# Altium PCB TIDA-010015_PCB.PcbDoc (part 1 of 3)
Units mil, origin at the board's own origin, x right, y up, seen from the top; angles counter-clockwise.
Board outline 6299.21 x 3149.61 mil, 2 copper layers (Top Layer, Bottom Layer), stack 64.6 mil thick; 232 components, 110 nets, 524 pads, 83 vias.
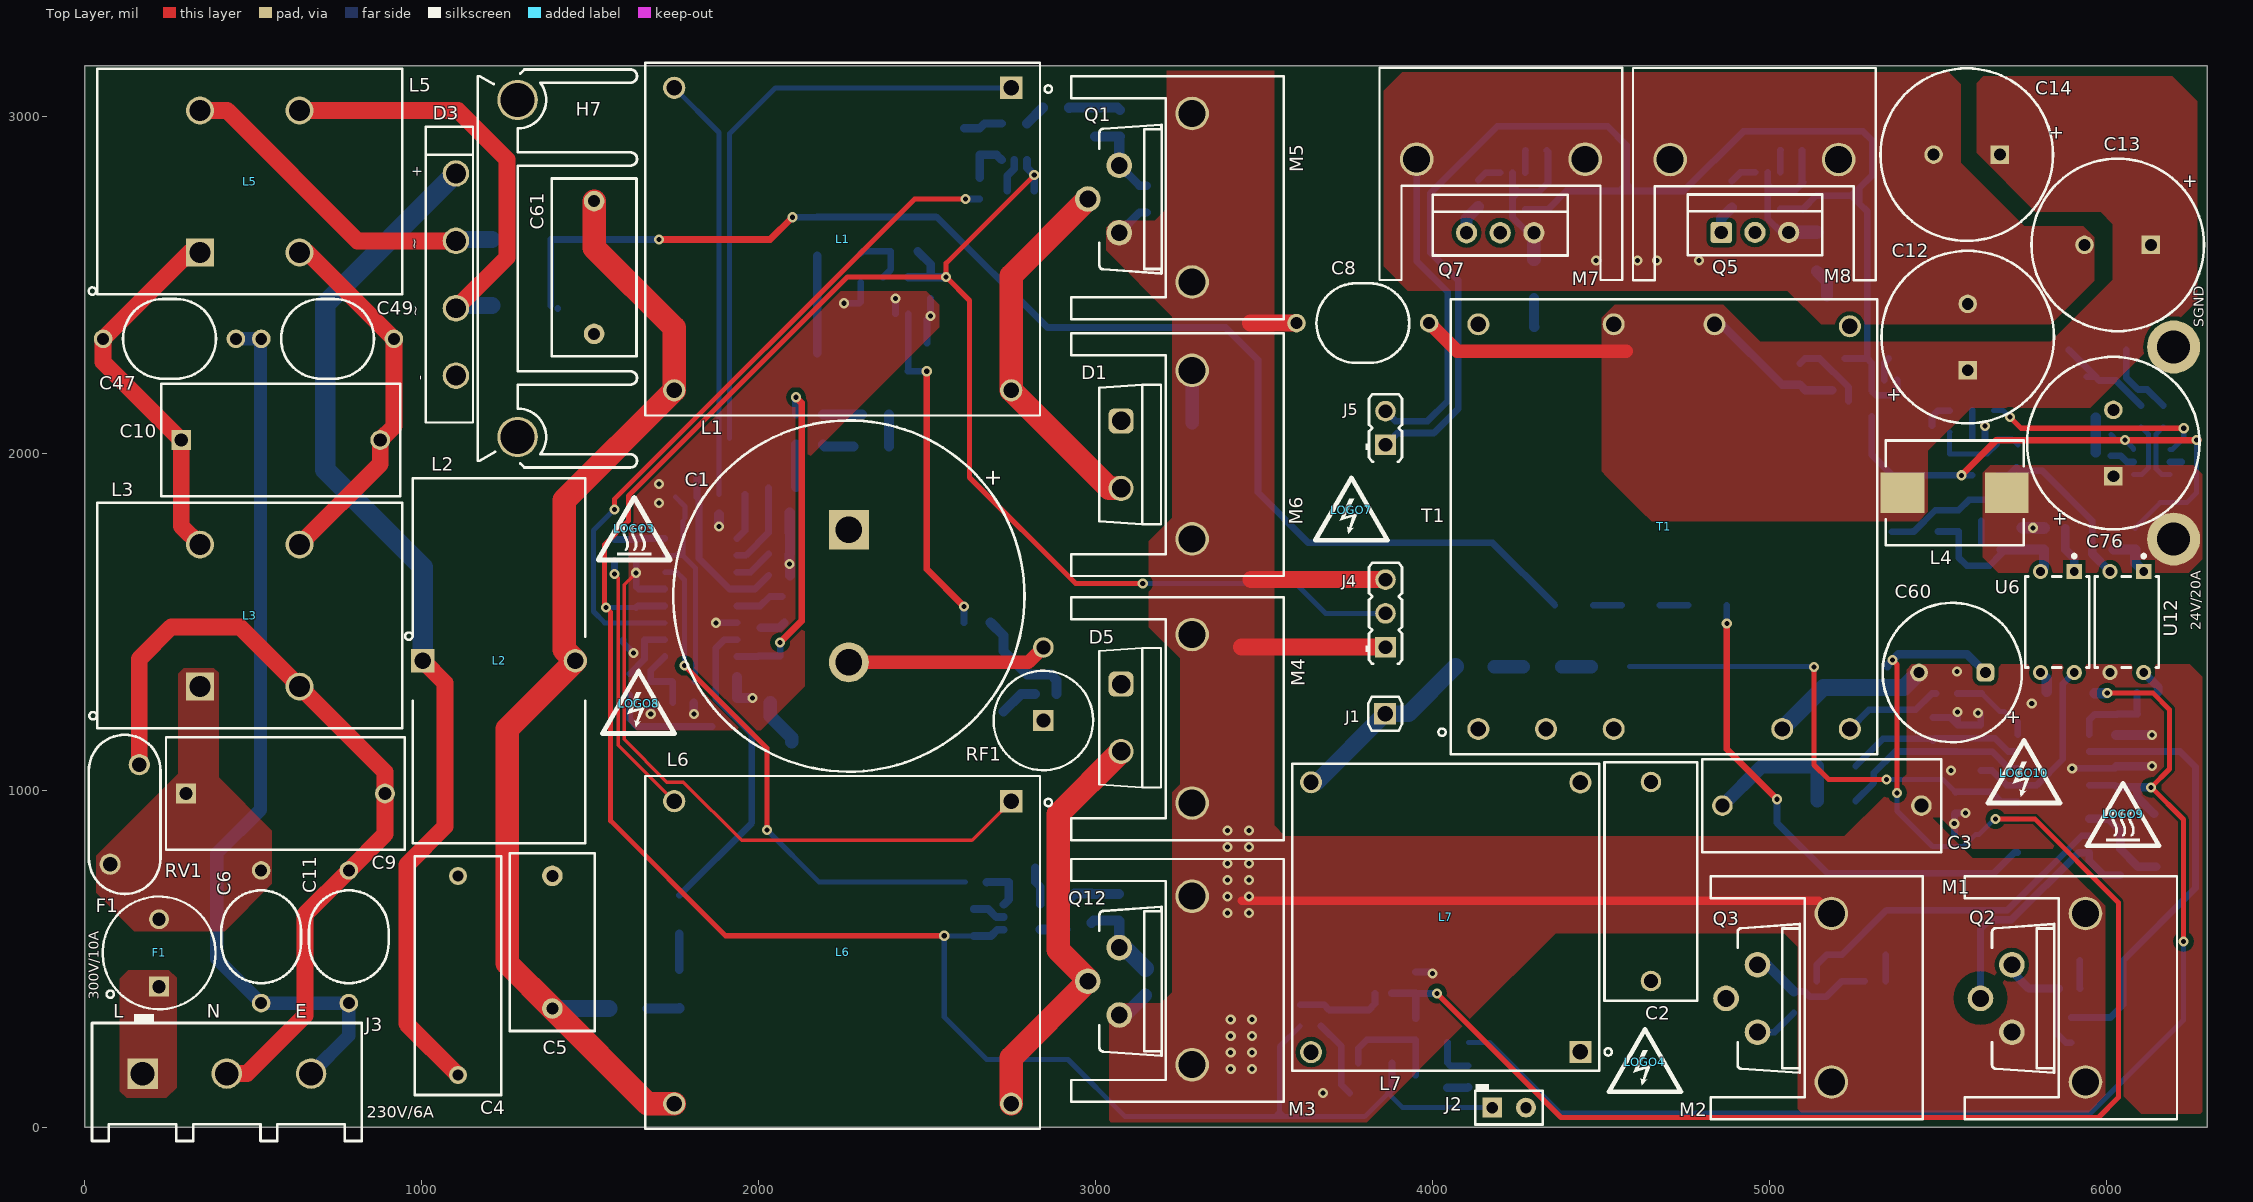
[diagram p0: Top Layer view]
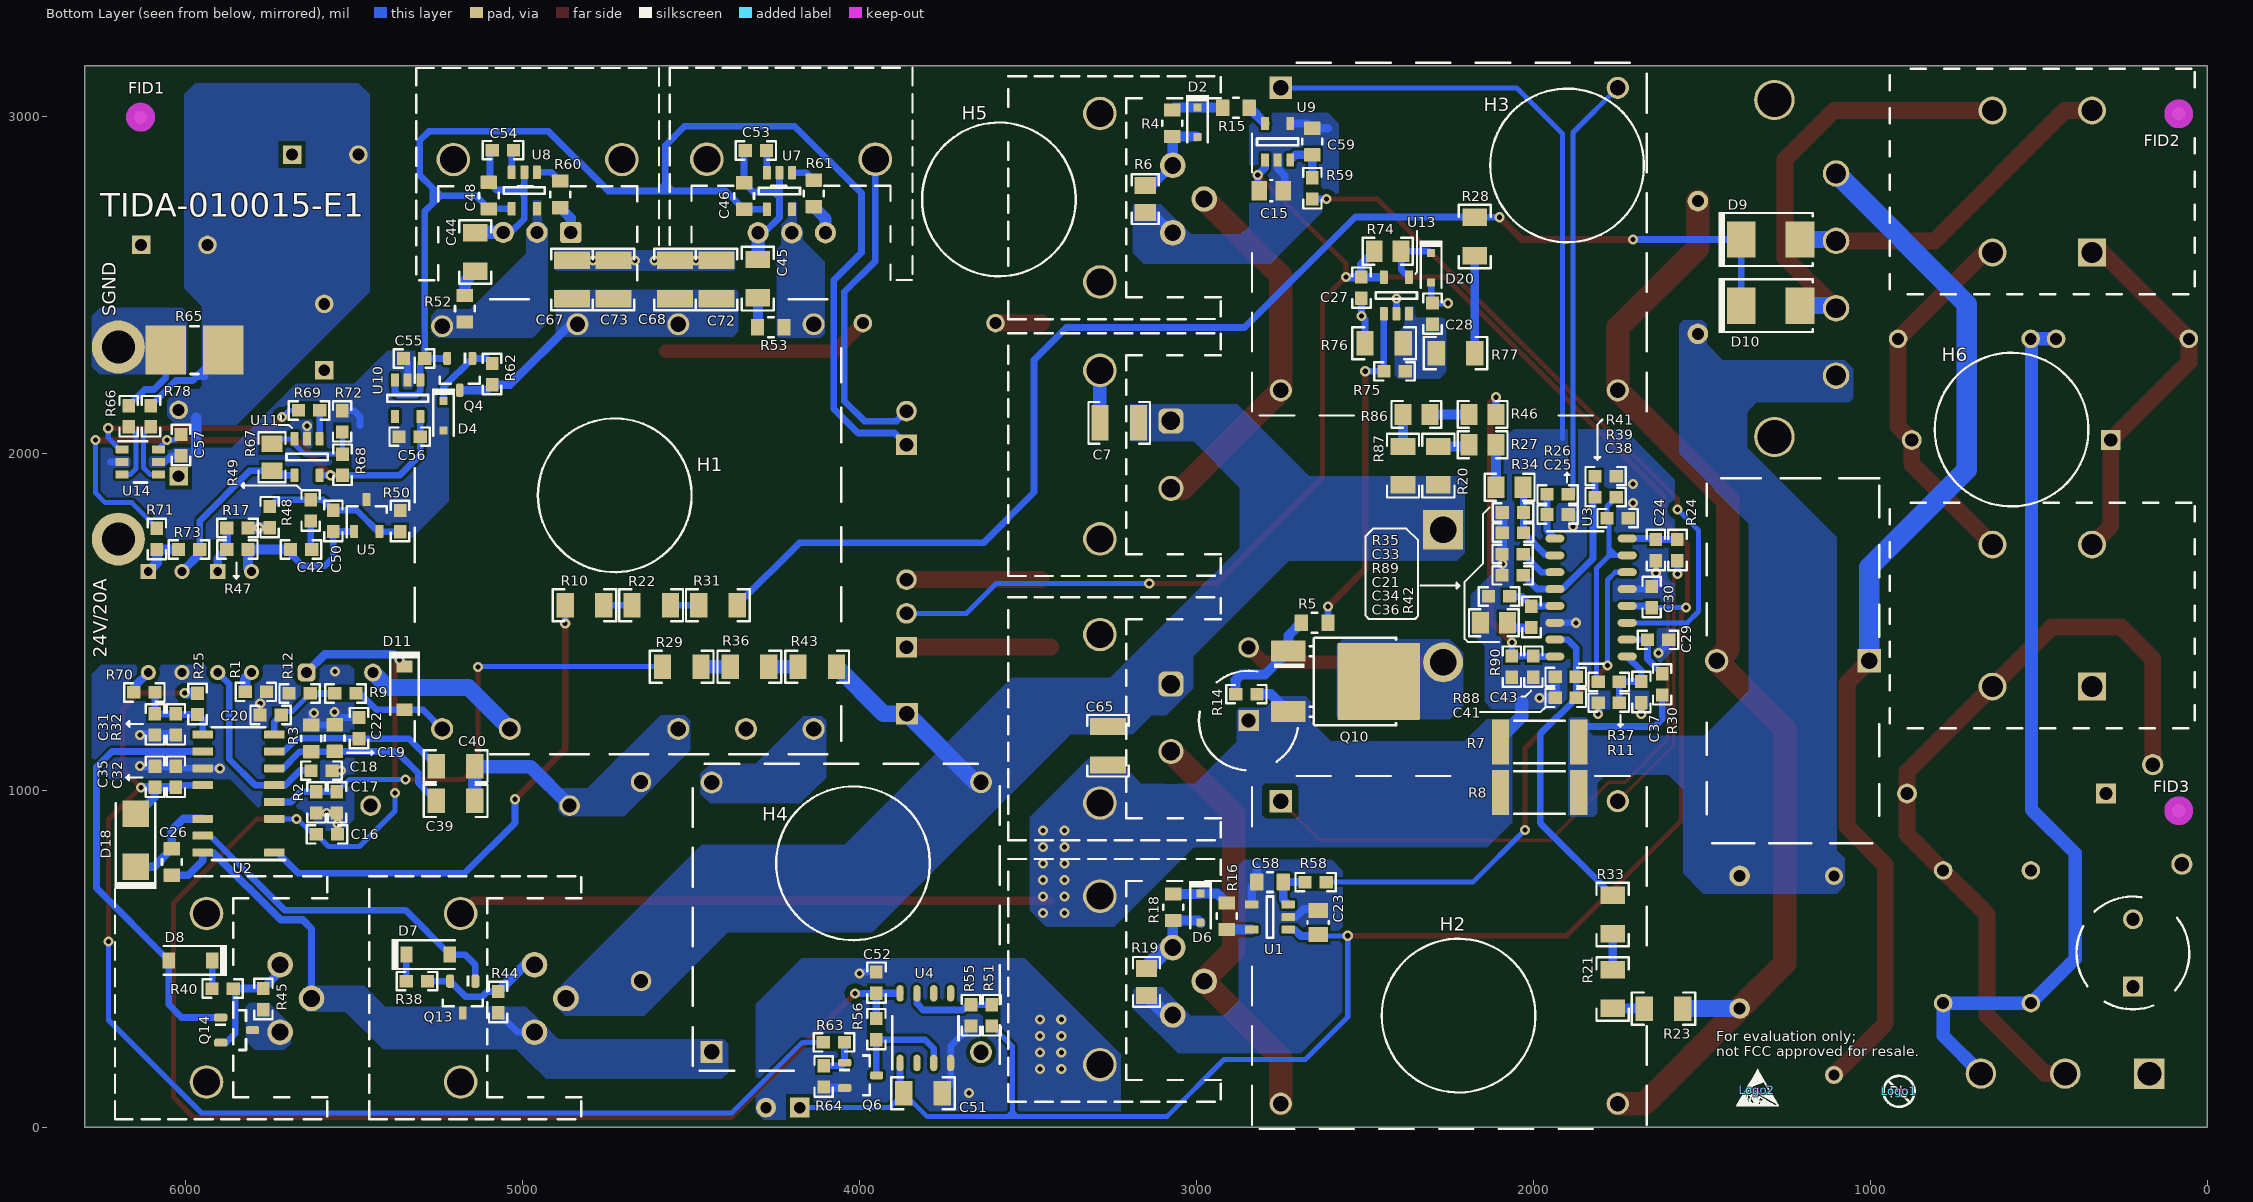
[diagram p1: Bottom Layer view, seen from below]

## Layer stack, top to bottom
Top Solder: solder mask 0.4, Solder Resist, Dk 3.5
Top Layer: signal copper 2.8
Dielectric1: core 59, FR-4 High Tg, Dk 4.8
Bottom Layer: signal copper 2.8
Bottom Solder: solder mask 0.4, Solder Resist, Dk 3.5

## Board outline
0,0 0,3149.61 6299.21,3149.61 6299.21,0

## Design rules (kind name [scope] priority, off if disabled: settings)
AcuteAngle [All] p1: minimum=4.50000000000000E+0001 checktracksonly=FALSE
AssemblyTestPointUsage [All] p1: valid=2
BoardOutlineClearance [All] p1: gap=15 ignorepadtopadclearanceinfootprint=FALSE
Clearance HV_ALL [InNetClass('HV')] p1: gap=60 ignorepadtopadclearanceinfootprint=FALSE
Clearance Clearance_1 [InNet('NetR10_2') vs InNet('PGND')] p2: gap=60 ignorepadtopadclearanceinfootprint=FALSE except(0: Arc-Hole Track-Hole SMDPad-Hole THPad-Hole Via-Hole Fill-Hole Poly-Hole Region-Hole Text-Hole)
Clearance Clearance_390V_Discrete [InNet('390V') vs InNet('NetR20_1') Or InNet('NetR86_2') Or InNet('NetQ3_1') Or InNet('SW') Or IsKeepOut] p3: gap=24 ignorepadtopadclearanceinfootprint=FALSE except(0: Arc-Hole Track-Hole SMDPad-Hole THPad-Hole Via-Hole Fill-Hole Poly-Hole Region-Hole Text-Hole)
Clearance Clearance_390V [InNet('390V')] p4: gap=59.05 ignorepadtopadclearanceinfootprint=FALSE except(0: Arc-Hole Track-Hole SMDPad-Hole THPad-Hole Via-Hole Fill-Hole Poly-Hole Region-Hole Text-Hole)
Clearance Clearance_MTG [InPadClass('MTG')] p5: gap=30 ignorepadtopadclearanceinfootprint=FALSE except(0: Arc-Hole Track-Hole SMDPad-Hole THPad-Hole Via-Hole Fill-Hole Poly-Hole Region-Hole Text-Hole)
Clearance Clearance_Keepouts [IsKeepOut] p6: gap=15 ignorepadtopadclearanceinfootprint=FALSE
Clearance Clearance_Poly [InPolygon] p7: gap=15 ignorepadtopadclearanceinfootprint=FALSE except(0: Arc-Hole Track-Hole SMDPad-Hole THPad-Hole Via-Hole Fill-Hole Poly-Hole Region-Hole Text-Hole; 8: Track-Poly SMDPad-Poly; 12: THPad-Poly; 20: Poly-Poly)
Clearance [All] p8: gap=7.7 ignorepadtopadclearanceinfootprint=FALSE except(0: Arc-Hole Track-Hole SMDPad-Hole THPad-Hole Via-Hole Fill-Hole Poly-Hole Region-Hole Text-Hole)
ComponentClearance ComponentClearance_MountingHoles_FiducialMarks [InComponentClass('Mounting Holes') vs InComponentClass('FiducialMark')] p1: gap=10 collisioncheckmode=3 verticalgap=10 showdistances=FALSE
ComponentClearance ComponentClearance_Shunt [InComponentClass('Header') vs InComponentClass('Shunt')] p2: gap=0 collisioncheckmode=3 verticalgap=0 showdistances=FALSE
ComponentClearance ComponentClearance_Logo [InComponentClass('Logo')] p3: gap=5 collisioncheckmode=3 verticalgap=5 showdistances=FALSE
ComponentClearance ComponentClearance_ScrewToNut [(HasFootprint('NY PMS 440 0025 PH')) vs (HasFootprint('Keystone_1902C'))] p4: gap=5 collisioncheckmode=3 verticalgap=5 showdistances=FALSE
ComponentClearance ComponentClearance_MountingHoles [InComponentClass('Mounting Holes')] p5: gap=50 collisioncheckmode=3 verticalgap=100000 showdistances=FALSE
ComponentClearance ComponentClearance_SmallPassives [HasFootprint('0201*') or HasFootprint('0402*') or HasFootprint('0508') or HasFootprint('0603*') or HasFootprint('0612') or HasFootprint('0805*') or HasFootprint('0815*') or HasFootprint('0830*') or HasFootprint('1206*') or HasFootprint('1210*') or HasFootprint('1808*') or HasFootprint('1812*') or HasFootprint('1825*') or HasFootprint('2010*') or HasFootprint('2220*') or HasFootprint('2225*') or HasFootprint('2512*') or HasFootprint('2728*') or HasFootprint('3518*') vs HasFootprint('0201*') or HasFootprint('0402*') or HasFootprint('0508') or HasFootprint('0603*') or HasFootprint('0612') or HasFootprint('0805*') or HasFootprint('0815*') or HasFootprint('0830*') or HasFootprint('1206*') or HasFootprint('1210*') or HasFootprint('1808*') or HasFootprint('1812*') or HasFootprint('1825*') or HasFootprint('2010*') or HasFootprint('2220*') or HasFootprint('2225*') or HasFootprint('2512*') or HasFootprint('2728*') or HasFootprint('3518*')] p6: gap=10 collisioncheckmode=3 verticalgap=10 showdistances=FALSE
ComponentClearance ComponentClearance_THtoSMT [IsThruComponent vs IsSMTComponent] p7: gap=5 collisioncheckmode=3 verticalgap=5 showdistances=FALSE
ComponentClearance ComponentClearance_THtoTH [IsThruComponent vs IsThruComponent] p8: gap=10 collisioncheckmode=3 verticalgap=10 showdistances=FALSE
ComponentClearance [All] p9: gap=10 collisioncheckmode=3 verticalgap=10 showdistances=FALSE
DiffPairsRouting [All] p1: maxlimit=100 minlimit=10 mostfreqgap=10 toplayer_minwidth=15 toplayer_maxwidth=15 toplayer_prefwidth=15 bottomlayer_minwidth=15 bottomlayer_maxwidth=15 bottomlayer_prefwidth=15 maxuncoupledlength=1000
FabricationTestPointUsage TestPointUsage [All] p1: valid=2 allowmultiple=FALSE
FabricationTestpoint Testpoint [All] p1: side=3 testpointundercomponent=TRUE minsize=40 maxsize=100 preferedsize=60 minholesize=0 maxholesize=40 preferedholesize=32 testpointgrid=1 allowsidetop=TRUE allowsidebottom=TRUE usegrid=TRUE gridtolerance=0.01
FanoutControl Fanout_LCC [IsLCC] p1: bgadir=Out bgaviamode=Centered fanoutstyle=Auto fanoutdirection=Alternating viagrid=1 // Fanout_LCC (Default Rule)
FanoutControl Fanout_BGA [IsBGA] p2: bgadir=Out bgaviamode=Centered fanoutstyle=Auto fanoutdirection=Alternating viagrid=1 // Fanout_BGA (Default Rule)
FanoutControl Fanout_Default [All] p4: bgadir=Out bgaviamode=Centered fanoutstyle=Auto fanoutdirection=Alternating viagrid=1 // Fanout_Default (Default Rule)
FanoutControl Fanout_Small [(CompPinCount < 5)] p5: bgadir=Out bgaviamode=Centered fanoutstyle=Auto fanoutdirection=OutThenIn viagrid=1 // Fanout_Small (Default Rule)
Height [All] p1: minheight=0 maxheight=1496.06 prefheight=500
HoleSize [All] p1: absolutevalues=TRUE maxlimit=251 minlimit=7.87 maxpercent=80.000 minpercent=20.000
MinimumAnnularRing MinimumAnnularRing_ThermalPadVias [IsVia and InAnyComponent] p1: minimumring=5.91
MinimumAnnularRing [All] p2: minimumring=5
MinimumSolderMaskSliver MinimumSolderMaskSliver_Logo [InComponentClass('Logo') vs InComponentClass('Logo')] p1: minsoldermaskwidth=0.7
MinimumSolderMaskSliver [All] p2: minsoldermaskwidth=3.94
PlaneConnect [All] p1: planeconnectstyle=Relief reliefexpansion=10 reliefentries=4 reliefconductorwidth=10 reliefairgap=10
PolygonConnect [All] p1: connectstyle=Direct reliefconductorwidth=10 reliefentries=4 polygonreliefangle="90 Angle" airgapwidth=10
RoutingVias [All] p1: holewidth=15 width=30 viastyle="Through Hole" minholewidth=7.87 minwidth=19.68 maxholewidth=40 maxwidth=65
RoutingVias ThermalPadVias [IsVia and InAnyComponent] p2: holewidth=7.87 width=19.68 viastyle="Through Hole" minholewidth=7.87 minwidth=19.68 maxholewidth=12.99 maxwidth=23.62
SilkToBoardRegionClearance [Not ((IsComment or IsDesignator) And (Hide <> 'False')) and not InRegion(1000,500,4000,800)] p1:
SilkToSilkClearance SilkToSilkClearance_Pb-FreeLogo [(HasFootprint('Pb-Free_Overlay_Medium') OR HasFootprint('Pb-Free_Overlay_Small')) vs (HasFootprint('Pb-Free_Overlay_Medium') OR HasFootprint('Pb-Free_Overlay_Small'))] p1: silktosilkclearance=0
SilkToSilkClearance [All] p2: silktosilkclearance=4
SilkToSolderMaskClearance SilkToComponentPadClearance [IsPad and InAnycomponent] p1: minsilkscreentomaskgap=5 clearancetoexposedcopper=TRUE
SilkToSolderMaskClearance "Silk to Solder Mask Opening" [All] p2: minsilkscreentomaskgap=4 clearancetoexposedcopper=FALSE
SolderMaskExpansion [All] p1: expansion=2.5
Width [All] p1: maxlimit=100 minlimit=6 preferedwidth=10 checkconnectedcopper=TRUE
14 further rules are at their usual default settings.

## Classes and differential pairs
component class Header: J1 J2 J4 J5
component class TIDA-010015_PFC: C1 C4 C5 C6 C7 C9 C10 C11 C15 C21 C23 C24 C25 C27 C28 C29 C30 C33 C34 C36 C37 C38 C41 C43 C47 C49 C58 C59 C61 C65 D1 D2 D3 D5 D6 D9 D10 D20 F1 H7 HS2 J3 L1 L2 L3 L5 L6 M1 M2 M3 M4 M5 M6 Q1 Q10 Q12 R4 R5 R6 R7 R8 R11 R14 R15 R16 R18 R19 R20 R21 R23 R24 R26 R27 R28 R30 R33 R34 R35 R37 R39 R41 R42 R46 R58 R59 R74 R75 R76 R77 R86 R87 R88 R89 R90 RF1 RV1 U1 U3 U9 U13
component class TIDA-010015-LLC: C2 C3 C8 C12 C13 C14 C16 C17 C18 C19 C20 C22 C26 C31 C32 C35 C39 C40 C42 C44 C45 C46 C48 C50 C51 C52 C53 C54 C55 C56 C57 C60 C67 C68 C72 C73 C76 D4 D7 D8 D11 D18 HS1 HS3 J1 J2 J4 J5 L4 L7 M7 M8 Q2 Q3 Q4 Q5 Q6 Q7 Q13 Q14 R1 R2 R3 R9 R10 R12 R17 R22 R25 R29 R31 R32 R36 R38 R40 R43 R44 R45 R47 R48 R49 R50 R51 R52 R53 R55 R56 R60 R61 R62 R63 R64 R65 R66 R67 R68 R69 R70 R71 R72 R73 R78 T1 U2 U4 U5 U6 U7 U8 U10 U11 U12 U14
net class HV: 390V NETA NetC2_2 NetC4_1 NetD1_3 NetD5_3 NetL7_2 NetR10_2 VAC
component class TIDA-010015_Hardware: FID1 FID2 FID3 H1 H2 H3 H4 H5 H6 Logo1 Logo2 LOGO3 LOGO4 Logo6 LOGO7 LOGO8 LOGO9 LOGO10 ZZ1 ZZ2 ZZ3 ZZ4
component class FiducialMark: FID1 FID2 FID3
component class AssemblyNote: ZZ1 ZZ2 ZZ3 ZZ4

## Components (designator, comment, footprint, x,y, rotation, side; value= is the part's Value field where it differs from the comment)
C1 "ESMR451VSN221MQ30S" SMQ_2540x2500 2268,1576 r270 top value=220uF
C2 "B32652A0473K000" B32652_1800x700x1250 4648,729 r90 top value=0.047uF
C3 "B32652A0473K000" B32652_1800x700x1250 5155,954 r0 top value=0.047uF
C4 "450MPK474J" MPK_1800x650 1108,450 r90 top value=0.47uF
C5 "ECW-FE2W334K" R46_1300x1200x600 1388,549 r90 top value=0.33µF
C6 "AY2222M35Y5US63L7" CD45_700x600x1100 524,565 r270 top value=2200pF
C7 "VJ1210Y471KXEAT5Z" 1210 3229,2090 r0 bottom value=470pF
C8 "AY2222M35Y5US63L7" CD45_700x600x1100 3793,2386 r180 top value=2200pF
C9 "B32922C3334K" B32922_14.5mm 596,990 r0 top value=0.33uF
C10 "B32922C3334K" B32922_14.5mm 582,2039 r0 top value=0.33uF
C11 "AY2222M35Y5US63L7" CD45_700x600x1100 784,565 r90 top value=2200pF
C12 "EEU-FS1H681B" FR_1250x2000 5588,2344.55 r90 top value=680uF
C13 "EEU-FS1H681B" FR_1250x2000 6033,2618 r180 top value=680uF
C14 "EEU-FS1H681B" FR_1250x2000 5585,2886 r180 top value=680uF
C15 "08053C225KAT2A" 0805_150 2778,2779 r0 bottom value=2.2uF
C16 "C1608X7R1H104K080AA" 0603 5580,869 r180 bottom value=0.1uF
C17 "GRM188R71C103KA01D" 0603 5550.47,964 r270 bottom value=0.01uF
C18 "885012006023" 0603 5596,1058 r180 bottom value=100pF
C19 "08055A3R3CAT2A" 0805_HV1 5557.41,1154.46 r90 bottom value=3.3pF
C20 "06035A100JAT2A" 0603 5747,1223 r0 bottom value=10pF
C21 "GRM188R71E682KA01D" 0603 2061.5,1637.5 r0 bottom value=6800pF
C22 "GRM188R71H682KA01D" 0603 5485,1184 r90 bottom value=6800pF
C23 "08053C225KAT2A" 0805_150 2638.66,607.4 r90 bottom value=2.2uF
C24 "C0603C220J5GACTU" 0603 1636.79,1712.27 r270 bottom value=22pF
C25 "C0603C220J5GACTU" 0603 1927.99,1818 r180 bottom value=22pF
C26 "C0805C104K1RACTU" 0805_HV1 6040,787 r270 bottom value=0.1uF
C27 "C0603C104J3RACTU" 0603 2510.42,2491 r270 bottom value=0.1uF
C28 "C0603C104J3RACTU" 0603 2299.42,2413.87 r90 bottom value=0.1uF
C29 "C1608X7R1H102K" 0603 1630,1446 r180 bottom value=1000pF
C30 "GRM188R71E105KA12D" 0603 1649,1573 r270 bottom value=1uF
C31 "06033D224KAT2A" 0603 6090.47,1195.34 r270 bottom value=0.22uF
C32 "GRM188R72A104KA35J" 0603 6028.47,1039.85 r90 bottom value=0.1uF
C33 "C1608X7R1H102K" 0603 2060.94,1764.04 r0 bottom value=1000pF
C34 "06035A821JAT2A" 0603 2102,1575 r0 bottom value=820pF
C35 "GRM188R61E475KE11D" 0603 6090.4,1039.85 r270 bottom value=4.7uF
C36 "0805YD225KAT2A" 0805_HV 2117,1496.7 r0 bottom value=2.2uF
C37 "GRM188R71E682KA01D" 0603 1679.99,1291.01 r270 bottom value=6800pF
C38 "GRM188R71H224KAC4D" 0603 1750,1807 r180 bottom value=0.22uF
C39 "GRM31A7U3A151JW31D" 1206 5198.28,968 r0 bottom value=150pF
C40 "GRM31A7U3A820JW31D" 1206 5198.28,1071 r0 bottom value=82pF
C41 "06031C102MAT2A" 0603 1904.01,1274 r0 bottom value=1000pF
C42 "06033C473JAT2A" 0603 5656.94,1714 r0 bottom value=0.047uF
C43 "GRM188R71H681KA01D" 0603 2000.5,1366.5 r270 bottom value=680pF
C44 "12061A331JAT2A" 1206 5140,2597 r270 bottom value=330pF
C45 "12061A331JAT2A" 1206 4301.45,2517.92 r270 bottom value=330pF
C46 "C0805C105K3RACTU" 0805_HV1 4342.32,2762.97 r90 bottom value=1uF
C47 "AY2222M35Y5US63L7" CD45_700x600x1100 252,2339.28 r0 top value=2200pF
C48 "C0805C105K3RACTU" 0805_HV1 5099.39,2764.22 r90 bottom value=1uF
C49 "AY2222M35Y5US63L7" CD45_700x600x1100 721.15,2339.28 r0 top value=2200pF
C50 "06035A100JAT2A" 0603 5561,1799 r270 bottom value=10pF
C51 "GRM319R61E105KC36D" 1206 3811.36,100.84 r180 bottom value=1uF
C52 "C1608X7R1H104K080AA" 0603 3949.49,428.68 r90 bottom value=0.1uF
C53 "GRM188R6YA225KA12D" 0603 4307.32,2897.97 r0 bottom value=2.2uF
C54 "GRM188R6YA225KA12D" 0603 5058,2899 r0 bottom value=2.2uF
C55 "C1608X5R1E105K080AC" 0603 5321.5,2280.89 r0 bottom value=1uF
C56 "GRT188R61C475KE13D" 0603 5334.5,2048.89 r0 bottom value=4.7uF
C57 "C1608X5R1E105K080AC" 0603 6013,2024 r270 bottom value=1uF
C58 "08055A101JAT2A" 0805_HV1 2781.87,727.4 r0 bottom value=100pF
C59 "08055A101JAT2A" 0805_HV1 2656,2924.48 r90 bottom value=100pF
C60 "EEU-FS1V102LB" Panasonic_1000x1250 5542,1349 r180 top value=1000µF
C61 "ECW-FE2W334K" R46_1300x1200x600 1512,2551 r270 top value=0.33µF
C65 "VJ1210Y471KXEAT5Z" 1210 3262,1131.91 r270 bottom value=470pF
C67 "C3225X7S2A475K200AE" 1210 4853,2515 r90 bottom value=4.7uF
C68 "C3225X7S2A475K200AE" 1210 4547,2515 r90 bottom value=4.7uF
C72 "C3225X7S2A475K200AE" 1210 4424,2515 r90 bottom value=4.7uF
C73 "C3225X7S2A475K200AE" 1210 4730,2515 r90 bottom value=4.7uF
C76 "EEU-FS1H681B" FR_1250x2000 6020,2030 r90 top value=680uF
D1 "MUR860G" TO-220AC 3075.54,1995.73 r270 top value=600V
D2 "BAT54HT1G" sod-323 2997,2982 r270 bottom value=0.35V
D3 "GBU2510-G" GBU 1102,2530 r270 top
D4 "BZX384-C15,115" SOD-323 5234,2111 r270 bottom value=15V
D5 "MUR860G" TO-220AC 3075.54,1214.87 r270 top value=600V
D6 "BAT54HT1G" sod-323 2988,650 r270 bottom value=0.35V
D7 "SD103BW-7-F" SOD-123 5280,512 r180 bottom value=30V
D8 "SD103BW-7-F" SOD-123 5985,495 r0 bottom value=30V
D9 "RS1MB-13-F" SMB 1296,2634 r180 bottom value=1000V
D10 "RS1MB-13-F" SMB 1296,2438 r180 bottom value=1000V
D11 "SD103BW-7-F" SOD-123 5350,1303 r270 bottom value=30V
D18 "US1J-13-F" SMA 6148,851 r90 bottom value=600V
D20 "BZT52C5V1S-7-F" SOD-323 2303.42,2550 r270 bottom value=5.1V
F1 "38321000000" FUSE_38321000000 221,517 r90 top value=10A
FID1 "Fiducial" Fiducial10-20 6133,2997 r180 bottom
FID2 "Fiducial" Fiducial10-20 85,3007 r180 bottom
FID3 "Fiducial" Fiducial10-20 85,939 r180 bottom
H1 "SJ-5303 (CLEAR)" Bumpon_SJ5003Transparent 4726,1875 r180 bottom
H2 "SJ-5303 (CLEAR)" Bumpon_SJ5003Transparent 2222,331 r180 bottom
H3 "SJ-5303 (CLEAR)" Bumpon_SJ5003Transparent 1900,2853.8 r180 bottom
H4 "SJ-5303 (CLEAR)" Bumpon_SJ5003Transparent 4018.97,783 r180 bottom
H5 "SJ-5303 (CLEAR)" Bumpon_SJ5003Transparent 3586,2753 r180 bottom
H6 "SJ-5303 (CLEAR)" Bumpon_SJ5003Transparent 581,2070 r180 bottom
H7 "V6560W" ASMN_V6560X 1285,2548 r270 top
J1 "61300111121" WURTH_61300111121 3859.25,1226.69 r0 top
J2 "800-10-002-10-001000" Mill-Max_800-10-002-10-001000 4227,58 r0 top
J3 "350429-1" TE_350429-1 422,159 r0 top
J4 "22284033" Molex_0022284033 3860.25,1524.66 r90 top
J5 "22284023" Molex_0022284023 3860.25,2074.66 r90 top
L1 "Custom" IND_PQ2625 2249.63,2635.38 r0 top value="150 µH"
L2 "7447076" IND_7447076 1230,1384 r0 top value=150uH
L3 "7448031501" WURTH_7448031501 490,1518 r0 top value=1mH
L4 "PA2607.301NLT" PA2607NL_7R5mm 5549,1882 r0 top value=300nH
L5 "7448031501" WURTH_7448031501 490,2806 r0 top value=1mH
L6 "Custom" IND_PQ2625 2249.63,518.38 r0 top value="150 µH"
L7 "" IND_PQ2020 4039,623 r180 top
Logo1 "Pb-Free Symbol" Pb-Free_Overlay_Small 915,106.17 r180 bottom
Logo2 "ESD Susceptible" ESD_Overlay_Small 1336,110 r180 bottom
LOGO3 "CAUTION HOT SURFACE" IEC_HotSurface_Small 1631,1776 r0 top
LOGO4 "DANGER HIGH VOLTAGE" IEC_HighVoltage_Small 4630,193 r0 top
Logo6 "FCC disclaimer" FCC_disclaimer 4405.61,-440 r0 top
LOGO7 "DANGER HIGH VOLTAGE" IEC_HighVoltage_Small 3759,1830 r0 top
LOGO8 "DANGER HIGH VOLTAGE" IEC_HighVoltage_Small 1644,1256 r0 top
LOGO9 "CAUTION HOT SURFACE" IEC_HotSurface_Small 6049,928 r0 top
LOGO10 "DANGER HIGH VOLTAGE" IEC_HighVoltage_Small 5755,1050 r0 top
M1 "WA-T220-101E" HEATSINK_WA-T220-101E 5894,384 r180 top
M2 "WA-T220-101E" HEATSINK_WA-T220-101E 5140,384 r180 top
M3 "WA-T220-101E" HEATSINK_WA-T220-101E 3243.17,435.3 r180 top locked
M4 "WA-T220-101E" HEATSINK_WA-T220-101E 3243.17,1211.72 r180 top
M5 "WA-T220-101E" HEATSINK_WA-T220-101E 3243.17,2758 r180 top
M6 "WA-T220-101E" HEATSINK_WA-T220-101E 3243.17,1995.72 r180 top
M7 "WA-T220-101E" HEATSINK_WA-T220-101E 4202.86,2828.79 r270 top
M8 "WA-T220-101E" HEATSINK_WA-T220-101E 4955,2828 r270 top
Q1 "IPP60R190P6" TO-220AB 3070.17,2754.01 r270 top value=650V
Q2 "IPP60R190P6" TO-220AB 5719,382 r270 top value=650V
Q3 "IPP60R190P6" TO-220AB 4964,382 r270 top value=650V
Q4 "MMBTA05LT1G" SOT-23 5186,2234 r270 bottom value="60 V"
Q5 "CSD19501KCS" KCS0003B#1 4956.7,2655.06 r90 top value=80V
Q6 "MMBT2222LT1G" SOT-23 3996.51,153.79 r180 bottom value="30 V"
Q7 "CSD19501KCS" KCS0003B#2 4200.7,2654.06 r90 top value=80V
Q10 "AOD4S60" DPAK 2593,1323 r180 bottom value=600V
Q12 "IPP60R190P6" TO-220AB 3070.17,432.93 r270 top value=650V
Q13 "BC858C-7-F" SOT-23 5177,386 r270 bottom value="30 V"
Q14 "BC858C-7-F" SOT-23 5848,288 r180 bottom value="30 V"
R1 "RNCF0603TKY10K0" 0603 5791,1292 r0 bottom value=10k
R2 "RNCF0603TKY10K0" 0603 5611.61,964 r90 bottom value=10k
R3 "RG2012P-201-B-T5" 0805_HV1 5626.41,1153.73 r270 bottom value=200
R4 "CRCW080518R2FKEA" 0805_HV1 3072,2979 r270 bottom value=18.2
R5 "CRCW080518R2FKEA" 0805_HV1 2649.24,1497 r180 bottom value=18.2
R6 "CRCW080510K0FKEA" 0805_HV 3152,2754.07 r90 bottom value=10.0k
R7 "CSRN2512FK30L0" 2512 1981.86,1143.24 r180 bottom value=0.03
R8 "CSRN2512FK30L0" 2512 1981.86,993 r180 bottom value=0.03
R9 "RT0603BRD0759K7L" 0603 5525,1287 r180 bottom value=59.7k
R10 "CRCW12061K00FKEA" 1206 4815.91,1549 r0 bottom value=1.00k
R11 "CRCW060366K5FKEA" 0603 1776.5,1259.5 r0 bottom value=66.5k
R12 "CRCW060310K0FKEA" 0603 5661,1287 r180 bottom value=10.0k
R14 "ERJ-3EKF4992V" 0603 2852,1285 r180 bottom value=49.9k
R15 "CRCW08052R20JNEA" 0805_HV1 2882.63,3024.91 r0 bottom value=2.2
R16 "CRCW08052R20JNEA" 0805_HV1 2910,626 r90 bottom value=2.2
R17 "CRCW06036K04FKEA" 0603 5845.77,1778.03 r180 bottom value=6.04k
R18 "CRCW080518R2FKEA" 0805_HV1 3069,652.52 r270 bottom value=18.2
R19 "CRCW080510K0FKEA" 0805_HV 3148,431 r90 bottom value=10.0k
R20 "CRCW12063M00JNEA" 1206 2282,1963 r270 bottom value=3.0Meg
R21 "CRCW12062M70JNEA" 1206 1765,410 r270 bottom value=2.7Meg
R22 "CRCW12061K00FKEA" 1206 4617.91,1549 r0 bottom value=1.00k
R23 "CRCW12062M70JNEA" 1206 1614,352 r180 bottom value=2.7Meg
R24 "CRCW060316K5FKEA" 0603 1572.68,1712.27 r90 bottom value=16.5k
R25 "CRCW0603750KFKEA" 0603 5964,1256 r90 bottom value=750k
R26 "CRCW060316K5FKEA" 0603 1927.99,1878 r180 bottom value=16.5k
R27 "CRCW08052M74FKEA" 0805_HV 2151,2024.84 r0 bottom value=2.74Meg
R28 "CRCW1206511KFKEA" 1206 2174,2643 r270 bottom value=511k
R29 "CRCW1206330KJNEA" 1206 4527.46,1366.54 r180 bottom value=330k
R30 "CRCW0603100RFKEA" 0603 1618,1314 r90 bottom value=100
R31 "CRCW12061K00FKEA" 1206 4419.91,1549 r0 bottom value=1.00k
R32 "CRCW0603487KFKEA" 0603 6028.47,1195.34 r90 bottom value=487k
R33 "CRCW12062M70JNEA" 1206 1765,631 r90 bottom value=2.7Meg
R34 "CRCW08052M74FKEA" 0805_HV 2070.94,1899.04 r0 bottom value=2.74Meg
R35 "CRCW0603133KFKEA" 0603 2060.94,1824.04 r180 bottom value=133k
R36 "CRCW1206330KJNEA" 1206 4326.46,1366.54 r180 bottom value=330k
R37 "CRCW060366K5FKEA" 0603 1776.5,1321.46 r180 bottom value=66.5k
R38 "CRCW060322R0JNEA" 0603 5313,433 r180 bottom value=22
R39 "CRCW060366K5FKEA" 0603 1785.5,1869.5 r180 bottom value=66.5k
R40 "CRCW060322R0JNEA" 0603 5889.48,411.17 r180 bottom value=22
R41 "CRCW060366K5FKEA" 0603 1785.5,1931.5 r180 bottom value=66.5k
R42 "CRCW06037K50FKEA" 0603 2006,1514 r270 bottom value=7.50k
R43 "CRCW1206374KFKEA" 1206 4125.46,1366.54 r180 bottom value=374k
R44 "CR0603-JW-472GLF" 0603 5072,371 r90 bottom value=4.7k
R45 "CR0603-JW-472GLF" 0603 5769,380 r90 bottom value=4.7k
R46 "CRCW08052M74FKEA" 0805_HV 2151,2115 r0 bottom value=2.74Meg
R47 "CRCW06036K04FKEA" 0603 5845.94,1714.03 r0 bottom value=6.04k
R48 "CRCW0603147KFKEA" 0603 5750,1810.03 r270 bottom value=147k
R49 "CRCW060310K0FKEA" 0603 5628.16,1830 r90 bottom value=10.0k
R50 "CRCW060316K9FKEA" 0603 5363,1798.5 r270 bottom value=16.9k
R51 "CRCW0603113KFKEA" 0603 3607,332 r270 bottom value=113k
R52 "CRCW080510R0JNEA" 0805_HV1 5170.69,2428.59 r90 bottom value=10
R53 "CRCW080510R0JNEA" 0805_HV1 4263,2374 r0 bottom value=10
R55 "RNCF0603TKY10K0" 0603 3669,332 r90 bottom value=10k
R56 "RT0603BRD07100KL" 0603 3949.92,290.84 r90 bottom value=100k
R58 "CRCW060310R0FKEAHP" 0603 2646,727 r0 bottom value=10.0
R59 "CRCW060310R0FKEAHP" 0603 2656,2786 r90 bottom value=10.0
R60 "CRCW08054R70JNEA" 0805_HV1 4888,2768 r90 bottom value=4.7
R61 "CRCW08054R70JNEA" 0805_HV1 4135.51,2770.85 r270 bottom value=4.7
R62 "RC0603FR-076K81L" 0603 5090,2234.7 r270 bottom value=6.81k
R63 "CRCW0603113KFKEA" 0603 4075.51,251.65 r180 bottom value=113k
R64 "RNCF0603TKY10K0" 0603 4106,150.5 r90 bottom value=10k
R65 "WSL2512L5000FEA18" WSL2512_-0005 5973,2306 r0 bottom value=0.0005
R66 "CRCW060310R0FKEAHP" 0603 6168.2,2109.6 r270 bottom value=10.0
R67 "CRCW08051M00FKEA" 0805_HV 5743,1988 r270 bottom value=1.00Meg
R68 "MCT06030C1004FP500" 0603 5533.87,1965.58 r270 bottom value=1.00Meg
R69 "ERJ-3EKF3303V" 0603 5633,2126.87 r180 bottom value=330k
R70 "CRCW0603487KFKEA" 0603 6122,1290 r180 bottom value=487k
R71 "CRCW06036K04FKEA" 0603 6085,1745.5 r90 bottom value=6.04k
R72 "RNCF0603TKY10K0" 0603 5535,2094.58 r270 bottom value=10k
R73 "CRCW06036K04FKEA" 0603 5989,1714.03 r0 bottom value=6.04k
R74 "CRCW080510K0FKEA" 0805_HV 2432.42,2599 r0 bottom value=10.0k
R75 "CRCW06031M10FKEA" 0603 2412,2242.91 r0 bottom value=1.10Meg
R76 "CRCW120649K9FKEA" 1206 2443,2325.91 r180 bottom value=49.9k
R77 "CRCW1206511KFKEA" 1206 2231,2296.91 r0 bottom value=511k
R78 "CRCW060310R0FKEAHP" 0603 6102.41,2109.6 r270 bottom value=10.0
R86 "CRCW08052M74FKEA" 0805_HV 2347,2115 r0 bottom value=2.74Meg
R87 "CRCW12062M70JNEA" 1206 2387,1963 r270 bottom value=2.7Meg
R88 "ERJ-3EKF1243V" 0603 1904.01,1336 r0 bottom value=124k
R89 "CRCW060395K3FKEA" 0603 2061.5,1700.5 r180 bottom value=95.3k
R90 "CRCW060382K5FKEA" 0603 2064,1366.5 r90 bottom value=82.5k
RF1 "EMC2-47RKI" RESADV550W80L2600D750B 2845,1315 r90 top value=47
RV1 "S10K275E2" VAR_S10K275E2 119,928 r270 top
T1 "PQ3230" IND_PQ3230 4687,1782 r90 top
U1 "UCC27517DBVR" DBV0005A_N 2781.87,623.4 r0 bottom
U2 "UCC25630DDB" DDB0014A 5842.47,989.85 r0 bottom
U3 "UCC28064DR" D0016A_N 1828.99,1571.7 r180 bottom
U4 "LP2951ACMX/NOPB" D0008A_L 3804.36,293.84 r90 bottom
U5 "TL431ACDBZR" DBZ0003A_N 5462,1815 r90 bottom
U6 "VO618A" DIP-4 5854,1499 r270 top
U7 "UCC24612-1DBVR" DBV0005A_N 4237.32,2777.97 r270 bottom
U8 "UCC24612-1DBVR" DBV0005A_N 4994.39,2779.22 r270 bottom
U9 "UCC27517DBVR" DBV0005A_N 2759,2924 r90 bottom
U10 "LP29681-50" DBV0005A_N 5340.44,2162.89 r270 bottom
U11 "TL331IDBVR" DBV0005A_N 5639.07,1988.5 r270 bottom
U12 "VO618A" DIP-4 6060,1499 r270 top
U13 "TLV171IDBVR" DBV0005A_N 2406.42,2468 r90 bottom
U14 "INA181A4IDBV" DBV0006A_N 6133.87,1974 r180 bottom
ZZ1 "This Assembly Note is for PCB labels only" AssemblyNoteLabel 750.08,5813.1 r0 top
ZZ2 "These assemblies are ESD sensitive, ESD precautions shall be observed." AssemblyNote 660.1,5722.37 r0 top
ZZ3 "These assemblies must be clean and free from flux and all contaminants. Use of no clean flux is not acceptable." AssemblyNote 660.1,5633.1 r0 top
ZZ4 "These assemblies must comply with workmanship standards IPC-A-610 Class 2, unless otherwise specified." AssemblyNote 660.1,5543.83 r0 top

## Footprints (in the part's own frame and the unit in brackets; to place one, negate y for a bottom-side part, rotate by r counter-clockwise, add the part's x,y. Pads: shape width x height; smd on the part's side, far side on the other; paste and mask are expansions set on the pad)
0603 [mm] "0603 from SM-752 data"
  rect 1x0.95 smd: 1(-0.8,0) 2(0.8,0)
  silkscreen extent -1.52,-0.69 1.52,0.69, body extent -0.87,-0.47 0.87,0.47, height 1
0805_150 [mm] "0805 / 1.5 mm height"
  rect 1.15x1.45 smd: 1(-0.9,0) 2(0.9,0)
  silkscreen extent -0.1,-0.8 0.1,0.8, body extent -1.1,-0.72 1.1,0.72, height 1.5
0805_HV [mil] "0805 with 30mil clearance between pads"
  rect 50x63 smd: 1(-40,0) 2(40,0)
  silkscreen extent -74,-40 74,40, body extent -43,-29 43,29, height 57
0805_HV1 [mm] "Custom footprint based on analyzing multiple manufacturer recommendations"
  rrect10% 1x1.25 smd: 1(-1,0) 2(1,0)
  silkscreen extent -0.2,-0.75 0.2,0.75, body extent -1.1,-0.72 1.1,0.73, height 1.45
1206 [mm] "1206 from SM-752 data"
  rect 1.3x1.85 smd: 1(-1.45,0) 2(1.45,0)
  silkscreen extent -2.4,-1.21 2.4,1.21, body extent -1.7,-0.9 1.7,0.9, height 1.35
1210 [mm] "1210 from SM-752 data"
  rect 1.3x2.7 smd: 1(-1.45,0) 2(1.45,0)
  silkscreen extent -2.32,-1.57 2.32,1.57, body extent -1.7,-1.35 1.7,1.35, height 1.35
2512 [mm] "Chip Resistor, Body 6.3x3.2mm, IPC Medium Density"
  rect 1.3x3.4 smd: 1(-2.95,0) 2(2.95,0)
  silkscreen extent -1.9,-1.6 1.9,1.6, body extent -3.22,-1.67 3.22,1.67, height 0.71
ASMN_V6560X [mm] "TH, 2-Leads, Body 29x12mm, Pitch 25.4mm"
  round 3.05 hole 2.55: 1(-12.7,0) 2(12.7,0)
  silkscreen extent -15,-3 15,9, body extent -15,-3 15,9, height 37.5
AssemblyNote [mil] "Assembly Note"
AssemblyNoteLabel [mil] "Assembly Note for PCB Labels"
B32652_1800x700x1250 [mm] "TH, 2-Leads, Body 18x7mm, Pin Spacing 15mm"
  round 1.55 hole 1.05: 1(-7.5,0) 2(7.5,0)
  silkscreen extent -9,-3.5 9,3.5, body extent -9,-3.5 9,3.5, height 12.5
B32922_14.5mm [mm] "Epcos film capacitors, 15mm spacing"
  rect 1.5x1.5 hole 1: 1(-7.5,0)
  round 1.5 hole 1: 2(7.5,0)
  silkscreen extent -9,-4.25 9,4.25, body extent -9,-4.25 9,4.25, height 14.5
Bumpon_SJ5003Transparent [mil] "3M Hemispherical Bumpon transparent"
  round 1 on Mech4: 0(0,0)
  silkscreen extent -228,-228 228,228, body extent -219,-219 219,219, height 197
CD45_700x600x1100 [mm] "TH, 2-Leads, Dia 7mm, Pin Spacing 10 mm"
  round 1.4 hole 0.9: 1(-5,0) 2(5,0)
  silkscreen extent -3.5,-3 3.5,3, body extent -5.34,-3.02 5.34,3.02, height 11
D0008A_L [mm] "SOIC, 8-Leads, Body 4.9x3.9mm, Pitch 1.27mm, IPC High Density"
  oval 1.25x0.55 smd: 1(-2.625,1.905) 2(-2.625,0.635) 3(-2.625,-0.635) 4(-2.625,-1.905) 5(2.625,-1.905) 6(2.625,-0.635) 7(2.625,0.635) 8(2.625,1.905)
  silkscreen extent -3.1,-2.5 0.9,2.5, body extent -3,-2.45 3,2.45, height 1.63
D0016A_N [mm] "SOIC, 16-Leads, Body 9.9x3.9mm, Pitch 1.27mm, IPC Medium Density"
  oval 1.45x0.6 smd: 1(-2.725,4.445) 2(-2.725,3.175) 3(-2.725,1.905) 4(-2.725,0.635) 5(-2.725,-0.635) 6(-2.725,-1.905) 7(-2.725,-3.175) 8(-2.725,-4.445) 9(2.725,-4.445) 10(2.725,-3.175) 11(2.725,-1.905) 12(2.725,-0.635) 13(2.725,0.635) 14(2.725,1.905) 15(2.725,3.175) 16(2.725,4.445)
  silkscreen extent -3.3,-5 0.9,5, body extent -3,-4.95 3,4.95, height 1.6
DBV0005A_N [mm] "SOT23, 5-Leads, Body 2.9x1.6mm, Pitch 0.95mm, Lead Span 2.8mm, IPC Medium Density"
  rrect17% 1x0.6 smd: 1(-1.375,0.95) 2(-1.375,0) 3(-1.375,-0.95) 4(1.375,-0.95) 5(1.375,0.95)
  silkscreen extent -0.25,-1.55 0.25,1.55, body extent -1.42,-1.46 1.42,1.46, height 1.09
DBV0006A_N [mm] "SOT23, 6-Leads, Body 2.9x1.6mm, Pitch 0.95mm, Lead Span 2.8mm, IPC Medium Density"
  rrect17% 1x0.6 smd: 1(-1.375,0.95) 2(-1.375,0) 3(-1.375,-0.95) 4(1.375,-0.95) 5(1.375,0) 6(1.375,0.95)
  silkscreen extent -1.68,-1.55 0.5,1.55, body extent -1.42,-1.46 1.42,1.46, height 1.12
DBZ0003A_N [mm] "SOT23, 3-Leads, Body 2.9x1.3mm, Pitch 0.95mm, Lead Span 2.4mm, IPC Medium Density"
  rrect17% 1x0.6 smd: 1(-1.2,0.95) 2(-1.2,-0.95) 3(1.2,0)
  silkscreen extent -1.65,-1.5 0.7,1.5, body extent -1.26,-1.46 1.26,1.46, height 0.98
DDB0014A [mm] "SMD, 14-Leads, Body 3.9x9.9mm, Pitch 1.27mm"
  rrect17% 1.55x0.6 smd: 1(-2.7,4.445) 3(-2.7,1.905) 4(-2.7,0.635) 5(-2.7,-0.635) 6(-2.7,-1.905) 7(-2.7,-3.175) 8(-2.7,-4.445) 9(2.7,-4.445) 10(2.7,-3.175) 11(2.7,-1.905) 12(2.7,-0.635) 14(2.7,1.905) 15(2.7,3.175) 16(2.7,4.445)
  silkscreen extent -3.5,-5 2,5, body extent -3.01,-4.95 3.01,4.95, height 1.75
DIP-4 [mm] "DIP, 4-Leads, Body 6.86x4.83mm, Pitch 2.54mm"
  rect 1.15x1.15 hole 0.65: 1(-3.81,1.27)
  round 1.15 hole 0.65: 2(-3.81,-1.27) 3(3.81,-1.27) 4(3.81,1.27)
  silkscreen extent -5.1,-2.41 3.43,2.41, body extent -4.02,-2.41 4.02,2.41, height 5.59
DPAK [mm] "D-PAK, 3-Pads, Body 6.22x6.73mm (max), TO-252AA using nominal STEP model"
  rrect6% 2.6x1.6 smd: 1(-3.4,2.28) 3(-3.4,-2.28)
  rrect2% 6.2x5.8 smd paste-2.9: 4(3.4,0)
  silkscreen extent -4.5,-3.3 4.7,3.28, body extent -3.86,-3.29 5.84,3.29, height 2.48
ESD_Overlay_Small [mil]
  silkscreen extent -62,-48 64,61
FCC_disclaimer [mil]
Fiducial10-20 [mm]
  round 1 smd mask+0.5: 1(0,0)
  Top Layer keep-out circle w1.178: c0,0 r0.5
FR_1250x2000 [mm] "TH, 2-Leads, Dia 12.5mm, Lead Spacing 5mm"
  rect 1.4x1.4 hole 0.9: 1(-2.5,0)
  round 1.4 hole 0.9: 2(2.5,0)
  silkscreen extent -6.5,-6.5 6.5,6.5, body extent -6.45,-6.49 6.49,6.49, height 22.01
FUSE_38321000000 [mm] "LITTELFUSE_383, TH-2P"
  rect 1.5x1.5 / inner round 1.5 / far side rect 1.5x1.5 hole 1: 1(-2.54,0)
  round 1.5 hole 1: 2(2.54,0)
  silkscreen extent -4.25,-4.25 4.25,4.25, body extent -4.25,-4.25 4.25,4.25, height 8
GBU [mm] "Comchip / Diodes Inc diode bridge"
  round 2 hole 1.5: 1(-7.62,0) 2(-2.54,0) 3(2.54,0) 4(7.62,0)
  silkscreen extent -11.15,-2.28 11.15,1.28, body extent -11.15,-2.28 11.15,1.28, height 21.55
HEATSINK_WA-T220-101E [mil] "HEATSINK VERT ALUM BLACK TO-220"
  round 99.69 hole 80: 1(-43.31,-250) 2(-43.31,250)
  silkscreen extent -315,-360 315,360, body extent -314,-360 315,360, height 1272
IEC_HighVoltage_Small [mil]
  silkscreen extent -107,-88 107,97
IEC_HotSurface_Small [mil]
  silkscreen extent -107,-93 107,92
IND_7447076 [mm] "IND, FIXED, TH-2P"
  rect 1.754x1.754 / inner round 1.754 / far side rect 1.754x1.754 hole 1.254: 1(-5.75,0)
  round 1.754 hole 1.254: 2(5.75,0)
  silkscreen extent -7.09,-13.75 6.5,13.75, body extent -6.5,-13.75 6.5,13.75, height 27.5
IND_PQ2020 [mm] "INDUCTOR, COIL FORMER, 14-PIN, TH"
  rect 1.659x1.659 / inner round 1.659 / far side rect 1.659x1.659 hole 1.159 paste+0 mask+0.05: 1(-10.15,10.15)
  round 1.659 hole 1.159 paste+0 mask+0.05: 2(-10.15,-10.15) 3(10.15,-10.17) 4(10.15,10.17)
  silkscreen extent -12.52,-11.58 11.58,11.58, body extent -11.58,-11.58 11.58,11.58, height 22
IND_PQ2625 [mm] "INDUCTOR, COIL FORMER, 12-PIN, TH"
  rect 1.673x1.673 hole 1.173 paste+0 mask+0.05: 1(12.7,11.4)
  round 1.673 hole 1.173 paste+0 mask+0.05: 2(-12.7,11.4) 3(-12.7,-11.4) 4(12.7,-11.4)
  silkscreen extent -14.87,-13.3 15.77,13.3, body extent -14.87,-13.3 14.87,13.3, height 26.05
IND_PQ3230 [mm] "INDUCTOR, COIL FORMER, 12-PIN, TH"
  round 1.659 hole 1.159 paste+0 mask+0.05: 1(-15.25,14) 2(-15.25,8.9) 3(-15.25,3.8) 5(-15.25,-8.9) 6(-15.25,-14) 7(15.103,-14) 8(15.25,-3.8) 9(15.25,3.8) 10(15.25,14)
  silkscreen extent -17.15,-16.07 17.15,17.02, body extent -17.15,-16.07 17.15,16.07, height 32.15
KCS0003B#1 [mm] "Flange Mount, 3-Leads, Body 10.16x4.51mm, Pitch 2.54mm"
  rrect25% 1.6x1.6 hole 1: 1(0,2.54)
  round 1.6 hole 1: 2(0,0) 3(0,-2.54)
  silkscreen extent -1.71,-5.08 2.86,5.08, body extent -1.71,-5.09 2.86,5.08, height 18.63
KCS0003B#2 [mm] "Flange Mount, 3-Leads, Body 10.16x4.51mm, Pitch 2.54mm"
  round 1.6 hole 1: 1(0,2.54) 2(0,0) 3(0,-2.54)
  silkscreen extent -1.71,-5.08 2.86,5.08, body extent -1.71,-5.09 2.86,5.08, height 18.63
Mill-Max_800-10-002-10-001000 [mm] "Mill-Max"
  rect 1.5x1.5 hole 0.85: 1(-1.27,0)
  round 1.5 hole 0.85: 2(1.27,0)
  silkscreen extent -2.54,-1.27 2.54,1.78, body extent -2.54,-1.27 2.54,1.27, height 8.13
Molex_0022284023 [mm] "Header, 2.54mm, 2x1, TH"
  rect 1.55x1.55 hole 1.02: 1(-1.27,0)
  round 1.55 hole 1.02: 2(1.27,0)
  silkscreen extent -2.54,-1.24 2.54,1.5, body extent -2.54,-1.24 2.54,1.24, height 8.4
Molex_0022284033 [mm] "Header, 2.54mm, 3x1, TH"
  rect 1.55x1.55 hole 1.02: 1(-2.54,0)
  round 1.55 hole 1.02: 2(0,0) 3(2.54,0)
  silkscreen extent -3.81,-1.24 3.81,1.5, body extent -3.81,-1.24 3.81,1.24, height 8.4
MPK_1800x650 [mm] "TH, 2-Leads, Body 18x6.5mm, Lead Spacing 15mm"
  round 1.35 hole 0.85: 1(-7.5,0) 2(7.5,0)
  silkscreen extent -9,-3.25 9,3.25, body extent -9,-3.25 9,3.25, height 12
PA2607NL_7R5mm [mm] "SMD, 2-Leads, Body 10.31x7.5mm"
  rect 3.3x3.05 smd: 1(-3.935,0) 2(3.935,0)
  silkscreen extent -5.2,-3.95 5.2,3.95, body extent -5.44,-3.95 5.44,3.95, height 7.5
Panasonic_1000x1250 [mm] "TH, 2-Leads, Dia 10mm, Lead Spacing 5mm"
  rrect50% 1.35x1.35 hole 0.85: 1(-2.5,0)
  round 1.35 hole 0.85: 2(2.5,0)
  silkscreen extent -5.25,-5.25 5.25,5.25, body extent -5.25,-5.25 5.26,5.25, height 13.51
Pb-Free_Overlay_Small [mil]
  silkscreen extent -46,-46 46,46
R46_1300x1200x600 [mm] "KEMET"
  round 1.55 hole 0.9: 1(-5,0) 2(5,0)
  silkscreen extent -6.7,-3.2 6.7,3.2, body extent -6.6,-3.1 6.6,3.1, height 12.1
RESADV550W80L2600D750B [mm] "RESISTOR, WIREWOUND, TH-2P, VERTICAL MOUNT"
  rect 1.554x1.554 / inner round 1.554 / far side rect 1.554x1.554 hole 1.054: 1(-2.75,0)
  round 1.554 hole 1.054: 2(2.75,0)
  silkscreen extent -6.5,-3.75 1,3.75, body extent -6.47,-3.74 1,3.74, height 29
SMA [mm] "Molded Diode, 2-Leads, Body 4.3x2.6mm, IPC Medium Density, based on OnSemi component dimensions and land pattern"
  rect 2x2 smd: 1(-2,0) 2(2,0)
  silkscreen extent -3.66,-1.57 2.79,1.57, body extent -2.6,-1.3 2.6,1.3, height 2.42
SMB [mil] "Molded Diode, 2-Leads, Body 5.4x3.6mm, IPC Medium Density, based on OnSemi component dimensions"
  rect 85x107.99 smd: 1(-87.01,0) 2(87.01,0)
  silkscreen extent -155,-82 125,82, body extent -106,-71 106,71, height 91
SMQ_2540x2500 [mm] "United Chemi-Con"
  rect 3x3 hole 2: 1(-5,0)
  round 3 hole 2: 2(5,0)
  silkscreen extent -13.24,-13.23 13.24,13.24, body extent -13.1,-13.18 13.16,13.18, height 27.01
SOD-123 [mm] "On Semi recommended land pattern"
  rect 0.915x1.22 smd: 1(-1.637,0) 2(1.637,0)
  silkscreen extent -2.74,-1.17 2.03,1.17, body extent -1.93,-0.9 1.93,0.9, height 1.35
sod-323 [mm] "NXP recommended land pattern"
  rect 0.6x0.6 smd paste-0.05: 1(-1.1,0) 2(1.1,0)
  silkscreen extent -2.06,-0.86 1.53,0.86, body extent -1.3,-0.67 1.3,0.68, height 1.1
SOD-323 [mm] "NXP recommended land pattern"
  rect 0.6x0.6 smd paste-0.05: 1(-1.1,0) 2(1.1,0)
  silkscreen extent -2.06,-0.86 1.53,0.86, body extent -1.3,-0.67 1.3,0.68, height 1.1
SOT-23 [mm] "SOT23, 3-Leads, Body 2.9x1.3mm, Pitch 0.95mm, Lead Span 2.5mm, IPC Medium Density"
  rrect50% 1x0.6 smd: 1(-1.2,0.95) 2(-1.2,-0.95) 3(1.2,0)
  silkscreen extent -1.63,-1.5 0.7,1.5, body extent -1.16,-1.45 1.21,1.45, height 1
TE_350429-1 [mm] "Header(Shrouded), 6.35mm, 3x1, TH"
  rect 2.3x2.3 hole 1.78: 1(-6.35,0)
  round 2.3 hole 1.78: 2(0,0) 3(6.35,0)
  silkscreen extent -10.16,-5.08 10.16,4.5, body extent -12.7,-5.08 12.7,3.81, height 14.83
TO-220AB [mil] "Copied from Altium's version of TO3B"
  round 76 hole 50: 1(-100,0) 2(-0.07,-93.17) 3(100,0)
  silkscreen extent -221,-59 221,126, body extent -221,-59 221,126, height 765
TO-220AC [mm]
  rrect50% 1.9x1.9 hole 1.4: 1(-2.54,0)
  round 1.9 hole 1.4: 3(2.54,0)
  silkscreen extent -5.25,-1.64 5.26,3.01, body extent -5.25,-1.64 5.26,3.01, height 19.09
VAR_S10K275E2 [mm] "EPCOS"
  round 1.6 hole 1.1: 1(-3.75,1.1) 2(3.75,-1.1)
  silkscreen extent -6,-2.7 6,2.7, body extent -5.98,-2.7 5.98,2.7, height 14.99
WSL2512_-0005 [mm]
  rect 3.05x3.68 smd: 1(-2.16,0) 2(2.16,0)
  silkscreen extent -0.3,-1.8 0.3,1.8, body extent -3.3,-1.71 3.3,1.71, height 0.89
WURTH_7448031501 [mm] "FILTER, COMMON MODE CHOKE, VERTICAL, TH-4P"
  rect 2.1x2.1 / inner round 2.1 / far side rect 2.1x2.1 hole 1.6: 1(-3.75,-5.35)
  round 2.1 hole 1.6: 2(3.75,-5.35) 3(3.75,5.35) 4(-3.75,5.35)
  silkscreen extent -12.09,-8.5 11.5,8.5, body extent -11.5,-8.5 11.5,8.5, height 25
WURTH_61300111121 [mm] "Header, 2.54 mm, 1x1, TH"
  rect 1.65x1.65 hole 1.15: 1(0,0)
  silkscreen extent -1.27,-1.27 1.27,1.27, body extent -1.27,-1.27 1.27,1.27, height 8.54

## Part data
C1: library part CMP-0010055-2, "CAP ALUM 220UF 20% 450V SNAP", Cap_Case=25.4x25mm, Manufacturer=Chemi-Con, Supplier Part Number 1=565-4511-ND, Tolerance_%=20%, Value1=Unknown, Value2=450V, ValueDisplayed=220uF
C2 C3: library part B32652A7153J000, "CAP FILM 0.047UF 10% 1KVDC RAD", Cap_Case=18x7x12.5, Manufacturer="EPCOS (TDK)", Supplier Part Number 1=495-6867-ND, Tolerance_%=5, Value2=1250V, ValueDisplayed=0.047µF
C4: "CAP, Film, 0.47 µF, 450 V, +/- 5%, TH", Cap_Case=18x6.5mm, Manufacturer=Rubycon, Supplier Part Number 1=1189-1824-ND, Tolerance_%=5, Value1=Unknown, Value2=450V, ValueDisplayed=0.47µF
C5 C61: library part CMP-0012558-3, "0.33µF Film Capacitor 450V Polypropylene (PP), Metallized Radial", Cap_Case=13x12x6, Manufacturer="Panasonic Electronic Components", Supplier Part Number 1=399-9643-ND, Tolerance_%=10%, Value1=Unknown, Value2=450V, ValueDisplayed=0.33µF
C6 C8 C11 C47 C49: "CAP, CERM, 2200 pF, 300 V, +/- 20%, Y5U, AEC-Q200 Grade 1, D9.5xT5mm", Cap_Case=9.5x5mm, Manufacturer=Vishay-Bccomponents, Supplier Part Number 1=BC2914-ND, TempCo=Y5U, Tolerance_%=20, Value1=Unknown, Value2=300V, ValueDisplayed=2200pF
C7 C65: "CAP, CERM, 470 pF, 500 V, +/- 10%, X7R, 1210", Cap_Case=1210, Manufacturer=Vishay-Vitramon, Supplier Part Number 1=720-1054-1-ND, TempCo=X7R, Tolerance_%=10, Value1=Unknown, Value2=500V, ValueDisplayed=470pF
C9 C10: "CAP, Film, 0.33 µF, X2 305 VAC, +/- 10%, TH", Cap_Case=18x8x14.5mm, Manufacturer=TDK, Supplier Part Number 1=495-5051-ND, Tolerance_%=10, ValueDisplayed=0.33µF
C12 C13 C14 C76: library part CMP-0010351-2, "680µF 50V Aluminum Electrolytic Capacitors Radial, Can 10000 Hrs @ 105°C", Manufacturer="Panasonic Electronic Components", Supplier Part Number 1=P122333CT-ND, Tolerance_%=20%, Value2=35V, ValueDisplayed=680uF
C15 C23: library part CMP-0007573-2, "CAP, CERM, 2.2 uF, 25 V, +/- 10%, X7R, 0805", Cap_Case=0805, Manufacturer=AVX, Supplier Part Number 1=478-5719-1-ND, TempCo=X7R, Tolerance_%=10%, Value1=Unknown, Value2=25V, ValueDisplayed=2.2uF
C16 C52: library part CMP-0007044-5, "CAP, CERM, 0.1 uF, 50 V, +/- 10%, X7R, 0603", Cap_Case=0603, Manufacturer=TDK, Supplier Part Number 1=445-1314-1-ND, TempCo=X7R, Tolerance_%=10%, Value1="0.0296 ohm", Value2=50V, ValueDisplayed=0.1uF
C17: library part CMP-0007377-4, "CAP, CERM, 0.01 uF, 16 V, +/- 10%, X7R, 0603", Cap_Case=0603, Manufacturer=MuRata, Supplier Part Number 1=490-1525-1-ND, TempCo=X7R, Tolerance_%=10%, Value1=Unknown, Value2=16V, ValueDisplayed=0.01uF
C18: library part C0603C101J5GAC, "CAP CER 100PF 16V C0G/NP0 0603", Cap_Case=0603, Manufacturer="Wurth Electronics Inc.", Supplier Part Number 1=732-7766-1-ND, TempCo=C0G/NP0, Tolerance_%=5, Value1=Unknown, Value2=16V, ValueDisplayed=100pF
C19: "CAP, CERM, 3.3 pF, 50 V, +/- 8%, C0G/NP0, 0805", Cap_Case=0805, Manufacturer=AVX, Supplier Part Number 1=478-1298-1-ND, TempCo=C0G/NP0, Tolerance_%=8, Value1="3.467 ohm", Value2=50V, ValueDisplayed=3.3pF
C20: "CAP, CERM, 10 pF, 50 V, +/- 5%, C0G/NP0, 0603", Cap_Case=0603, Manufacturer=AVX, Supplier Part Number 1=478-1163-1-ND, TempCo=C0G/NP0, Tolerance_%=5, Value1="0.403 ohm", Value2=50V, ValueDisplayed=10pF
C21 C37: library part CMP-0007427-4, "CAP, CERM, 6800 pF, 25 V, +/- 10%, X7R, 0603", Cap_Case=0603, Manufacturer=MuRata, Supplier Part Number 1=81-GRM18R71E682KA01D, TempCo=X7R, Tolerance_%=10%, Value1=Unknown, Value2=25V, ValueDisplayed=6800pF
C22: "CAP, CERM, 6800 pF, 50 V, +/- 10%, X7R, 0603", Cap_Case=0603, Manufacturer=MuRata, Supplier Part Number 1=490-1508-1-ND, TempCo=X7R, Tolerance_%=10, Value1=Unknown, Value2=50V, ValueDisplayed=6800pF
C24 C25: "CAP, CERM, 22 pF, 50 V, +/- 5%, C0G/NP0, 0603", Cap_Case=0603, Manufacturer=Kemet, Supplier Part Number 1=399-1053-1-ND, TempCo=C0G/NP0, Tolerance_%=5, Value1=Unknown, Value2=50V, ValueDisplayed=22pF
C26: "CAP, CERM, 0.1 µF, 100 V,+/- 10%, X7R, 0805", Cap_Case=0805, Manufacturer=Kemet, Supplier Part Number 1=399-3486-1-ND, TempCo=X7R, Tolerance_%=10, Value1="0.064 ohm", Value2=100V, ValueDisplayed=0.1µF
C27 C28: library part CMP-0006856-5, "CAP, CERM, 0.1 uF, 25 V, +/- 5%, X7R, 0603", Cap_Case=0603, Manufacturer=Kemet, Supplier Part Number 1=399-1282-1-ND, TempCo=X7R, Tolerance_%=5%, Value1=Unknown, Value2=25V, ValueDisplayed=0.1uF
C29 C33: "CAP, CERM, 1000 pF, 50 V, +/- 10%, X7R, 0603", Cap_Case=0603, Manufacturer=TDK, Supplier Part Number 1=445-1308-1-ND, TempCo=X7R, Tolerance_%=10, Value1="0.24 ohm", Value2=50V, ValueDisplayed=1000pF
C30: "CAP, CERM, 1 µF, 25 V, +/- 10%, X7R, 0603", Cap_Case=0603, Manufacturer=MuRata, Supplier Part Number 1=490-5307-1-ND, TempCo=X7R, Tolerance_%=10, Value1=Unknown, Value2=25V, ValueDisplayed=1µF
C31: "CAP, CERM, 0.22 µF, 25 V, +/- 10%, X5R, 0603", Cap_Case=0603, Manufacturer=AVX, Supplier Part Number 1=478-1245-1-ND, TempCo=X5R, Tolerance_%=10, Value1="0.036 ohm", Value2=25V, ValueDisplayed=0.22µF
C32: "CAP, CERM, 0.1 µF, 100 V, +/- 10%, X7R, 0603", Cap_Case=0603, Manufacturer=MuRata, Supplier Part Number 1=490-6439-1-ND, TempCo=X7R, Tolerance_%=10, Value1=Unknown, Value2=100V, ValueDisplayed=0.1µF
